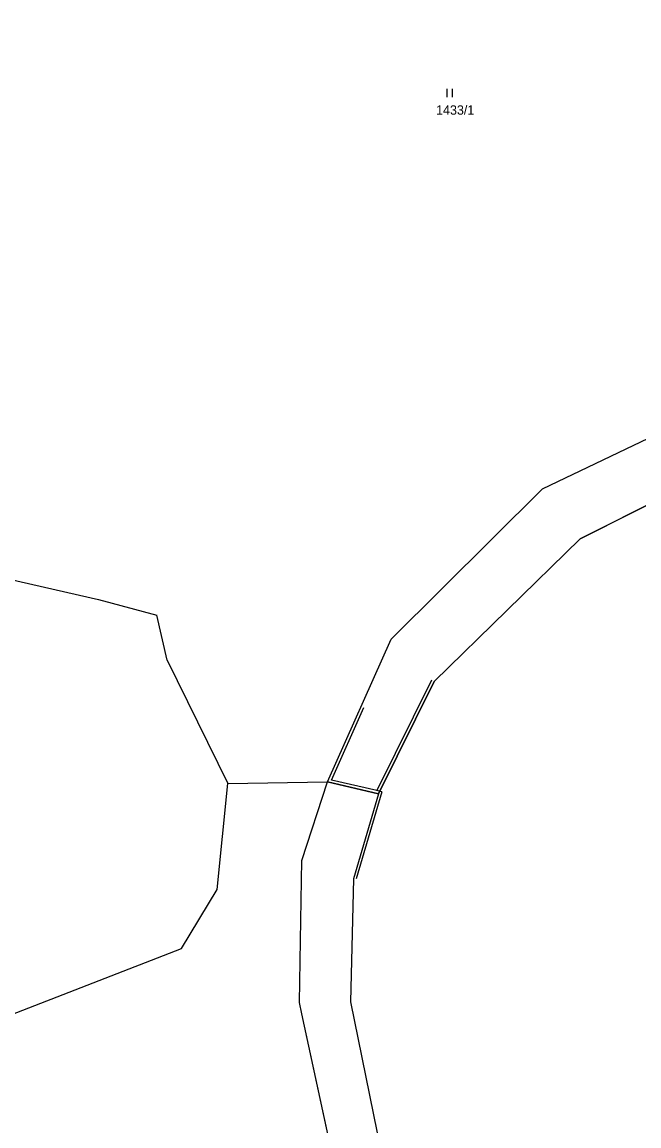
# Model space of a CAD drawing. Extents: x -779618 to -776429, y -1144546 to -1143350.
# Drawn here: x -779418.1 to -779305.8, y -1143790.9 to -1143590 of the extents above; entities that cross this region are included whole.
import ezdxf

# ---------------------------------------------------------------- set-up
doc = ezdxf.new("R2010")
doc.units = 0
for name, color, linetype in [('1', 7, 'Continuous'), ('11', 7, 'Continuous'), ('2', 7, 'Continuous'), ('3', 7, 'Continuous'), ('4', 7, 'Continuous')]:
    doc.layers.add(name, color=color, linetype=linetype)

msp = doc.modelspace()

# ---------------------------------------------------------------- linework, layer by layer
at = {"layer": '1'}
for p, q in [((-779323.37, -1143674.94), (-779275.9, -1143652.24)), ((-779267.05, -1143659.19), (-779316.51, -1143684.05)), ((-779350.91, -1143702.29), (-779323.37, -1143674.94)), ((-779450.72, -1143684.57), (-779404.2, -1143695.11)), ((-779316.51, -1143684.05), (-779343.13, -1143710.02)), ((-779404.2, -1143695.11), (-779393.61, -1143697.95)), ((-779391.74, -1143706.15), (-779393.61, -1143697.95)), ((-779362.52, -1143728.3), (-779350.91, -1143702.29)), ((-779391.74, -1143706.15), (-779380.7, -1143728.59)), ((-779343.13, -1143710.02), (-779353.27, -1143730.44)), ((-779382.61, -1143747.84), (-779380.7, -1143728.59)), ((-779380.7, -1143728.59), (-779362.52, -1143728.3)), ((-779367.21, -1143742.56), (-779362.52, -1143728.3)), ((-779353.27, -1143730.44), (-779362.52, -1143728.3)), ((-779353.27, -1143730.44), (-779357.81, -1143745.9)), ((-779367.45, -1143757.12), (-779367.21, -1143742.56)), ((-779357.81, -1143745.9), (-779358.36, -1143768.31)), ((-779389.13, -1143758.58), (-779382.61, -1143747.84)), ((-779367.64, -1143768.46), (-779367.45, -1143757.12)), ((-779421.27, -1143771.11), (-779389.13, -1143758.58)), ((-779367.2, -1143770.5), (-779367.64, -1143768.46)), ((-779358.36, -1143768.31), (-779348.2, -1143817.85)), ((-779360.96, -1143799.38), (-779367.2, -1143770.5))]:
    msp.add_line(p, q, dxfattribs=at)
at = {"layer": '11'}
msp.add_lwpolyline([(-779360.96, -1143799.38), (-779367.2, -1143770.5), (-779367.64, -1143768.46), (-779367.45, -1143757.12), (-779367.21, -1143742.56), (-779362.52, -1143728.3), (-779353.27, -1143730.44), (-779343.13, -1143710.02), (-779316.51, -1143684.05), (-779267.05, -1143659.19), (-779258.15, -1143654.55), (-779152.58, -1143602.83), (-779126.05, -1143590.02)], dxfattribs=at)
at = {"layer": '3'}
for p, q in [((-779340.77, -1143602.19), (-779340.77, -1143603.69)), ((-779339.77, -1143603.69), (-779339.77, -1143602.19))]:
    msp.add_line(p, q, dxfattribs=at)
at = {"layer": '4'}
for p, q in [((-779343.58, -1143709.8), (-779353.54, -1143729.86)), ((-779361.82, -1143727.95), (-779355.93, -1143714.77)), ((-779353.54, -1143729.86), (-779361.82, -1143727.95)), ((-779352.64, -1143730.07), (-779357.29, -1143745.9)), ((-779352.64, -1143730.07), (-779353.54, -1143729.86))]:
    msp.add_line(p, q, dxfattribs=at)

# ---------------------------------------------------------------- texts
at = {"layer": '2'}
msp.add_text('1433/1', height=1.7, dxfattribs=at).set_placement((-779342.75, -1143606.87))

doc.saveas('drawing.dxf')
